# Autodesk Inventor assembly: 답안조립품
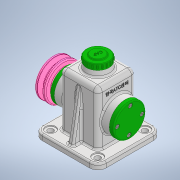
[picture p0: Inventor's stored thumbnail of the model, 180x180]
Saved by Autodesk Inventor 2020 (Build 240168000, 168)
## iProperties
Created: 2021-07
Part Number: 답안조립품
Document SubType Name: Assembly
Designer: Owner
Author: Owner
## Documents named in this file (14)
- C:\Users\Owner\Desktop\710715V1012\답안조립품.iam
- C:\Users\Owner\Desktop\710715V1012\본체.ipt
- C:\Users\Owner\Desktop\710715V1012\베어링 15 x 35 x 11.ipt
- C:\Users\Owner\Desktop\710715V1012\축.ipt
- C:\Users\Owner\Desktop\710715V1012\멈춤링 15 x 1.ipt
- C:\Users\Owner\Desktop\710715V1012\앞커버.ipt
- C:\Users\Owner\Desktop\710715V1012\뒤커버.ipt
- C:\Users\Owner\Desktop\710715V1012\오일실 15 25 7.ipt
- C:\Users\Owner\Desktop\710715V1012\볼트 M4 x 10.ipt
- C:\Users\Owner\Desktop\710715V1012\상부캡.ipt
- C:\Users\Owner\Desktop\710715V1012\키 5 x 5 x 14.ipt
- C:\Users\Owner\Desktop\710715V1012\V-벨트풀리.ipt
- C:\Users\Owner\Desktop\710715V1012\와셔.ipt
- C:\Users\Owner\Desktop\710715V1012\볼트 M6 x 12.ipt
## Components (1 placed, 1 different names)
1. V-벨트풀리:1 — 플러쉬:1
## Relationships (1: Flush 1)
- 플러쉬:1 [Flush]: V-벨트풀리:1
